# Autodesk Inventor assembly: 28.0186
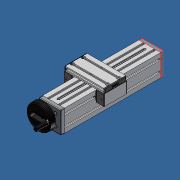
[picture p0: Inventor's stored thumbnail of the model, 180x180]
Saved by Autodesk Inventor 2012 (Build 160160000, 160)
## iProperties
Created: 2007-06
Part Number: 28.0186
Document SubType Name: Assembly
Designer: Andy Moles
Description: ADJ UNIT VEN 90
Title: ADJUSTING UNIT VEN 90
Author: Andy Moles
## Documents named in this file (19)
- C:\Andys Backup Data\ANDY'S INVENTOR\INVENTOR LIBRARIES\PARTS LIBRARY\READY FOR USE MODULES LG\28.0186 ADJUSTING UNIT VEN 90.iam
- C:\Andys Backup Data\ANDY'S INVENTOR\INVENTOR LIBRARIES\PARTS LIBRARY\READY FOR USE MODULES LG\SUBCOMPONENTS\50.1264 BALL BEARING 10X30X9 6200 2RS DIN 625.ipt
- C:\Andys Backup Data\ANDY'S INVENTOR\INVENTOR LIBRARIES\PARTS LIBRARY\READY FOR USE MODULES LG\SUBCOMPONENTS\28.0205 BEARING PLATE 90X90 HANDWHEEL SIDE.ipt
- C:\Andys Backup Data\ANDY'S INVENTOR\INVENTOR LIBRARIES\PARTS LIBRARY\READY FOR USE MODULES LG\SUBCOMPONENTS\28.0206 BEARING PLATE 90X90 IDLER SIDE.ipt
- C:\Andys Backup Data\ANDY'S INVENTOR\INVENTOR LIBRARIES\PARTS LIBRARY\READY FOR USE MODULES LG\SUBCOMPONENTS\28.0204 HANDWHEEL 100mm.iam
- C:\Andys Backup Data\ANDY'S INVENTOR\INVENTOR LIBRARIES\PARTS LIBRARY\FASTENING ELEMENTS\NUTS\21.1351 M8 SQUARE NUT.ipt
- C:\Andys Backup Data\ANDY'S INVENTOR\INVENTOR LIBRARIES\PARTS LIBRARY\FASTENING ELEMENTS\SCREWS CAP\21.1204 M8X25.ipt
- C:\Andys Backup Data\ANDY'S INVENTOR\INVENTOR LIBRARIES\PARTS LIBRARY\READY FOR USE MODULES LG\SUBCOMPONENTS\28.0216_1 90x90S.ipt
- C:\Andys Backup Data\ANDY'S INVENTOR\INVENTOR LIBRARIES\PARTS LIBRARY\READY FOR USE MODULES LG\SUBCOMPONENTS\28.0221 ACME SCREW 16X4.ipt
- C:\Andys Backup Data\ANDY'S INVENTOR\INVENTOR LIBRARIES\PARTS LIBRARY\FASTENING ELEMENTS\WASHERS\21.1326 DISC SPRING 20.ipt
- C:\Andys Backup Data\ANDY'S INVENTOR\INVENTOR LIBRARIES\PARTS LIBRARY\READY FOR USE MODULES LG\SUBCOMPONENTS\28.0224_1 LWN 32X45-90 90X19-NSC.ipt
- C:\Andys Backup Data\ANDY'S INVENTOR\INVENTOR LIBRARIES\PARTS LIBRARY\READY FOR USE MODULES LG\SUBCOMPONENTS\28.0255 Nut slide connector 20.ipt
- C:\Andys Backup Data\ANDY'S INVENTOR\INVENTOR LIBRARIES\PARTS LIBRARY\READY FOR USE MODULES LG\SUBCOMPONENTS\28.0126 SLIDE 45X32.ipt
- C:\Andys Backup Data\ANDY'S INVENTOR\INVENTOR LIBRARIES\PARTS LIBRARY\FASTENING ELEMENTS\SCREWS CAP\21.1200 M8X16.ipt
- C:\Andys Backup Data\ANDY'S INVENTOR\INVENTOR LIBRARIES\PARTS LIBRARY\FASTENING ELEMENTS\SCREWS CAP\21.1235 M5X16.ipt
- C:\Andys Backup Data\ANDY'S INVENTOR\INVENTOR LIBRARIES\PARTS LIBRARY\COMPONENTS LG\22.1095 SLIDE RAIL LN.iam
- C:\Andys Backup Data\ANDY'S INVENTOR\INVENTOR LIBRARIES\PARTS LIBRARY\END CAPS\22.1003_1 END CAP 45x32 Z Gray.iam
- C:\Andys Backup Data\ANDY'S INVENTOR\INVENTOR LIBRARIES\PARTS LIBRARY\END CAPS\22.1014_1 END CAP 90X19 GRAY.ipt
- C:\Andys Backup Data\ANDY'S INVENTOR\INVENTOR LIBRARIES\PARTS LIBRARY\READY FOR USE MODULES LG\SUBCOMPONENTS\28.0257 BRONZE NUT 16X4 NOTCHED.ipt
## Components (40 placed, 18 different names)
1. 28.0216_1 90x90S:1 — Flush:9, Mate:9, Mate:10, Mate:11, Flush:10, Flush:11, Flush:12, Mate:13, Flush:13, Flush:14, Mate:25, Mate:27
2. 28.0204 HANDWHEEL 100mm:1 [sub-assembly] — Insert:4
3. 50.1264 10X30X9 6200 2RS DIN 625 BALL BEARING:1 — Insert:15
4. 50.1264 10X30X9 6200 2RS DIN 625 BALL BEARING:2 — Insert:14, Insert:18
5. 28.0205 BEARING PLATE 90X90 HANDWHEEL SIDE:1 — Insert:4, Insert:6, Insert:7, Insert:8, Insert:9, Insert:15, Flush:12, Mate:13, Flush:13, Flush:14
6. 28.0206 BEARING PLATE 90X90 IDLER SIDE:1 — Insert:10, Insert:11, Insert:12, Insert:13, Mate:11, Flush:10, Flush:11, Insert:14
7. 21.1204  M8 x 25:1 — Insert:6
8. 21.1204  M8 x 25:2 — Insert:7
9. 21.1204  M8 x 25:3 — Insert:8
10. 21.1204  M8 x 25:4 — Insert:9
11. 21.1204  M8 x 25:5 — Insert:10
12. 21.1204  M8 x 25:6 — Insert:11
13. 21.1204  M8 x 25:7 — Insert:12
14. 21.1204  M8 x 25:8 — Insert:13
15. 28.0221 ACME SCREW 16X4:1 — Insert:16, Insert:17, Mate:24
16. 21.1326 DISC SPRING 20:1 — Insert:16
17. 21.1326 DISC SPRING 20:2 — Insert:17, Insert:18
18. 28.0224_1 LWN 32X45-90 90X19-NSC:1 — Insert:19, Insert:20, Insert:21, Insert:22, Insert:23, Insert:24, Insert:25, Insert:26, Angle:4, Angle:5, Angle:6, Angle:7, Insert:27, Insert:28, Insert:29, Angle:8, Mate:15, Flush:15, Flush:16, Flush:18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
19. 28.0255 Nut slide connector 20:1 — Insert:29, Angle:8, Mate:26, Angle:13
20. 28.0126 SLIDE 45X32:1 — Mate:15, Flush:15, Flush:16, Mate:19, Flush:21, Mate:20, Insert:31, Insert:32, Angle:10, Angle:11
21. 28.0126 SLIDE 45X32:2 — Flush:18, Flush:19, Mate:16, Mate:17, Flush:20, Mate:18, Insert:30, Insert:33, Angle:9, Angle:12
22. 21.1200 M8 x 16:1 — Insert:19
23. 21.1200 M8 x 16:2 — Insert:20
24. 21.1200 M8 x 16:3 — Insert:21
25. 21.1200 M8 x 16:4 — Insert:22
26. 21.1235  M5 x 16:1 — Insert:27
27. 21.1235  M5 x 16:2 — Insert:28
28. 21.1351 M8 SQUARE NUT:2 — Insert:23, Angle:6
29. 21.1351 M8 SQUARE NUT:3 — Insert:24, Angle:7
30. 21.1351 M8 SQUARE NUT:4 — Insert:26, Angle:4
31. 21.1351 M8 SQUARE NUT:5 — Insert:25, Angle:5
32. 22.1095 SLIDE RAIL LN:1 [sub-assembly] — Mate:17, Flush:20, Mate:18, Mate:25, Mate:27
33. 22.1095 SLIDE RAIL LN:2 [sub-assembly] — Mate:19, Flush:21, Mate:20
34. 22.1003\1 END CAP 45x32 Z Gray:1 [sub-assembly] — Insert:30, Angle:12
35. 22.1003\1 END CAP 45x32 Z Gray:2 [sub-assembly] — Insert:33, Angle:9
36. 22.1003\1 END CAP 45x32 Z Gray:3 [sub-assembly] — Insert:31, Angle:11
37. 22.1003\1 END CAP 45x32 Z Gray:4 [sub-assembly] — Insert:32, Angle:10
38. 22.1014_1 END CAP 90X19 GRAY:1 — Mate:21, Flush:22, Flush:23
39. 22.1014_1 END CAP 90X19 GRAY:2 — Mate:22, Flush:24, Flush:25
40. 28.0257 BRONZE NUT 16X4 NOTCHED:1 — Mate:24, Mate:26, Angle:13
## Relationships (71: Insert 29, Flush 16, Mate 16, Angle 10)
- Insert:4: 28.0204 HANDWHEEL 100mm:1 ↔ 28.0205 BEARING PLATE 90X90 HANDWHEEL SIDE:1
- Insert:6: 28.0205 BEARING PLATE 90X90 HANDWHEEL SIDE:1 ↔ 21.1204  M8 x 25:1
- Insert:7: 28.0205 BEARING PLATE 90X90 HANDWHEEL SIDE:1 ↔ 21.1204  M8 x 25:2
- Insert:8: 28.0205 BEARING PLATE 90X90 HANDWHEEL SIDE:1 ↔ 21.1204  M8 x 25:3
- Insert:9: 28.0205 BEARING PLATE 90X90 HANDWHEEL SIDE:1 ↔ 21.1204  M8 x 25:4
- Insert:10: 28.0206 BEARING PLATE 90X90 IDLER SIDE:1 ↔ 21.1204  M8 x 25:5
- Insert:11: 28.0206 BEARING PLATE 90X90 IDLER SIDE:1 ↔ 21.1204  M8 x 25:6
- Insert:12: 28.0206 BEARING PLATE 90X90 IDLER SIDE:1 ↔ 21.1204  M8 x 25:7
- Insert:13: 28.0206 BEARING PLATE 90X90 IDLER SIDE:1 ↔ 21.1204  M8 x 25:8
- Flush:9: 28.0216_1 90x90S:1
- Mate:9: 28.0216_1 90x90S:1
- Mate:10: 28.0216_1 90x90S:1
- Mate:11: 28.0216_1 90x90S:1 ↔ 28.0206 BEARING PLATE 90X90 IDLER SIDE:1
- Flush:10: 28.0216_1 90x90S:1 ↔ 28.0206 BEARING PLATE 90X90 IDLER SIDE:1
- Flush:11: 28.0216_1 90x90S:1 ↔ 28.0206 BEARING PLATE 90X90 IDLER SIDE:1
- Insert:14: 50.1264 10X30X9 6200 2RS DIN 625 BALL BEARING:2 ↔ 28.0206 BEARING PLATE 90X90 IDLER SIDE:1
- Insert:15: 50.1264 10X30X9 6200 2RS DIN 625 BALL BEARING:1 ↔ 28.0205 BEARING PLATE 90X90 HANDWHEEL SIDE:1
- Flush:12: 28.0216_1 90x90S:1 ↔ 28.0205 BEARING PLATE 90X90 HANDWHEEL SIDE:1
- Mate:13: 28.0216_1 90x90S:1 ↔ 28.0205 BEARING PLATE 90X90 HANDWHEEL SIDE:1
- Flush:13: 28.0216_1 90x90S:1 ↔ 28.0205 BEARING PLATE 90X90 HANDWHEEL SIDE:1
- Flush:14: 28.0216_1 90x90S:1 ↔ 28.0205 BEARING PLATE 90X90 HANDWHEEL SIDE:1
- Insert:16: 28.0221 ACME SCREW 16X4:1 ↔ 21.1326 DISC SPRING 20:1
- Insert:17: 28.0221 ACME SCREW 16X4:1 ↔ 21.1326 DISC SPRING 20:2
- Insert:18: 50.1264 10X30X9 6200 2RS DIN 625 BALL BEARING:2 ↔ 21.1326 DISC SPRING 20:2
- Insert:19: 28.0224_1 LWN 32X45-90 90X19-NSC:1 ↔ 21.1200 M8 x 16:1
- Insert:20: 28.0224_1 LWN 32X45-90 90X19-NSC:1 ↔ 21.1200 M8 x 16:2
- Insert:21: 28.0224_1 LWN 32X45-90 90X19-NSC:1 ↔ 21.1200 M8 x 16:3
- Insert:22: 28.0224_1 LWN 32X45-90 90X19-NSC:1 ↔ 21.1200 M8 x 16:4
- Insert:23: 28.0224_1 LWN 32X45-90 90X19-NSC:1 ↔ 21.1351 M8 SQUARE NUT:2
- Insert:24: 28.0224_1 LWN 32X45-90 90X19-NSC:1 ↔ 21.1351 M8 SQUARE NUT:3
- Insert:25: 28.0224_1 LWN 32X45-90 90X19-NSC:1 ↔ 21.1351 M8 SQUARE NUT:5
- Insert:26: 28.0224_1 LWN 32X45-90 90X19-NSC:1 ↔ 21.1351 M8 SQUARE NUT:4
- Angle:4: 28.0224_1 LWN 32X45-90 90X19-NSC:1 ↔ 21.1351 M8 SQUARE NUT:4
- Angle:5: 28.0224_1 LWN 32X45-90 90X19-NSC:1 ↔ 21.1351 M8 SQUARE NUT:5
- Angle:6: 28.0224_1 LWN 32X45-90 90X19-NSC:1 ↔ 21.1351 M8 SQUARE NUT:2
- Angle:7: 28.0224_1 LWN 32X45-90 90X19-NSC:1 ↔ 21.1351 M8 SQUARE NUT:3
- Insert:27: 28.0224_1 LWN 32X45-90 90X19-NSC:1 ↔ 21.1235  M5 x 16:1
- Insert:28: 28.0224_1 LWN 32X45-90 90X19-NSC:1 ↔ 21.1235  M5 x 16:2
- Insert:29: 28.0224_1 LWN 32X45-90 90X19-NSC:1 ↔ 28.0255 Nut slide connector 20:1
- Angle:8: 28.0224_1 LWN 32X45-90 90X19-NSC:1 ↔ 28.0255 Nut slide connector 20:1
- Mate:15: 28.0224_1 LWN 32X45-90 90X19-NSC:1 ↔ 28.0126 SLIDE 45X32:1
- Flush:15: 28.0224_1 LWN 32X45-90 90X19-NSC:1 ↔ 28.0126 SLIDE 45X32:1
- Flush:16: 28.0224_1 LWN 32X45-90 90X19-NSC:1 ↔ 28.0126 SLIDE 45X32:1
- Flush:18: 28.0224_1 LWN 32X45-90 90X19-NSC:1 ↔ 28.0126 SLIDE 45X32:2
- Flush:19: 28.0224_1 LWN 32X45-90 90X19-NSC:1 ↔ 28.0126 SLIDE 45X32:2
- Mate:16: 28.0224_1 LWN 32X45-90 90X19-NSC:1 ↔ 28.0126 SLIDE 45X32:2
- Mate:17: 28.0126 SLIDE 45X32:2 ↔ 22.1095 SLIDE RAIL LN:1
- Flush:20: 28.0126 SLIDE 45X32:2 ↔ 22.1095 SLIDE RAIL LN:1
- Mate:18: 28.0126 SLIDE 45X32:2 ↔ 22.1095 SLIDE RAIL LN:1
- Mate:19: 28.0126 SLIDE 45X32:1 ↔ 22.1095 SLIDE RAIL LN:2
- Flush:21: 28.0126 SLIDE 45X32:1 ↔ 22.1095 SLIDE RAIL LN:2
- Mate:20: 28.0126 SLIDE 45X32:1 ↔ 22.1095 SLIDE RAIL LN:2
- Insert:30: 28.0126 SLIDE 45X32:2 ↔ 22.1003\1 END CAP 45x32 Z Gray:1
- Insert:31: 28.0126 SLIDE 45X32:1 ↔ 22.1003\1 END CAP 45x32 Z Gray:3
- Insert:32: 28.0126 SLIDE 45X32:1 ↔ 22.1003\1 END CAP 45x32 Z Gray:4
- Insert:33: 28.0126 SLIDE 45X32:2 ↔ 22.1003\1 END CAP 45x32 Z Gray:2
- Angle:9: 28.0126 SLIDE 45X32:2 ↔ 22.1003\1 END CAP 45x32 Z Gray:2
- Angle:10: 28.0126 SLIDE 45X32:1 ↔ 22.1003\1 END CAP 45x32 Z Gray:4
- Angle:11: 28.0126 SLIDE 45X32:1 ↔ 22.1003\1 END CAP 45x32 Z Gray:3
- Angle:12: 28.0126 SLIDE 45X32:2 ↔ 22.1003\1 END CAP 45x32 Z Gray:1
- Mate:21: 28.0224_1 LWN 32X45-90 90X19-NSC:1 ↔ 22.1014_1 END CAP 90X19 GRAY:1
- Flush:22: 28.0224_1 LWN 32X45-90 90X19-NSC:1 ↔ 22.1014_1 END CAP 90X19 GRAY:1
- Flush:23: 28.0224_1 LWN 32X45-90 90X19-NSC:1 ↔ 22.1014_1 END CAP 90X19 GRAY:1
- Mate:22: 28.0224_1 LWN 32X45-90 90X19-NSC:1 ↔ 22.1014_1 END CAP 90X19 GRAY:2
- Flush:24: 28.0224_1 LWN 32X45-90 90X19-NSC:1 ↔ 22.1014_1 END CAP 90X19 GRAY:2
- Flush:25: 28.0224_1 LWN 32X45-90 90X19-NSC:1 ↔ 22.1014_1 END CAP 90X19 GRAY:2
- Mate:24: 28.0221 ACME SCREW 16X4:1 ↔ 28.0257 BRONZE NUT 16X4 NOTCHED:1
- Mate:25: 28.0216_1 90x90S:1 ↔ 22.1095 SLIDE RAIL LN:1
- Mate:26: 28.0255 Nut slide connector 20:1 ↔ 28.0257 BRONZE NUT 16X4 NOTCHED:1
- Angle:13: 28.0255 Nut slide connector 20:1 ↔ 28.0257 BRONZE NUT 16X4 NOTCHED:1
- Mate:27: 28.0216_1 90x90S:1 ↔ 22.1095 SLIDE RAIL LN:1
